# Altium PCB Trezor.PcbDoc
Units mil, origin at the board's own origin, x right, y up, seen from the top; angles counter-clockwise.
Board outline 3500 x 3250 mil, 2 copper layers (Top, Bottom), stack 62 mil thick; 36 components, 17 nets, 131 pads, 2 vias.
Unrouted connection lines stored in the file: 20.
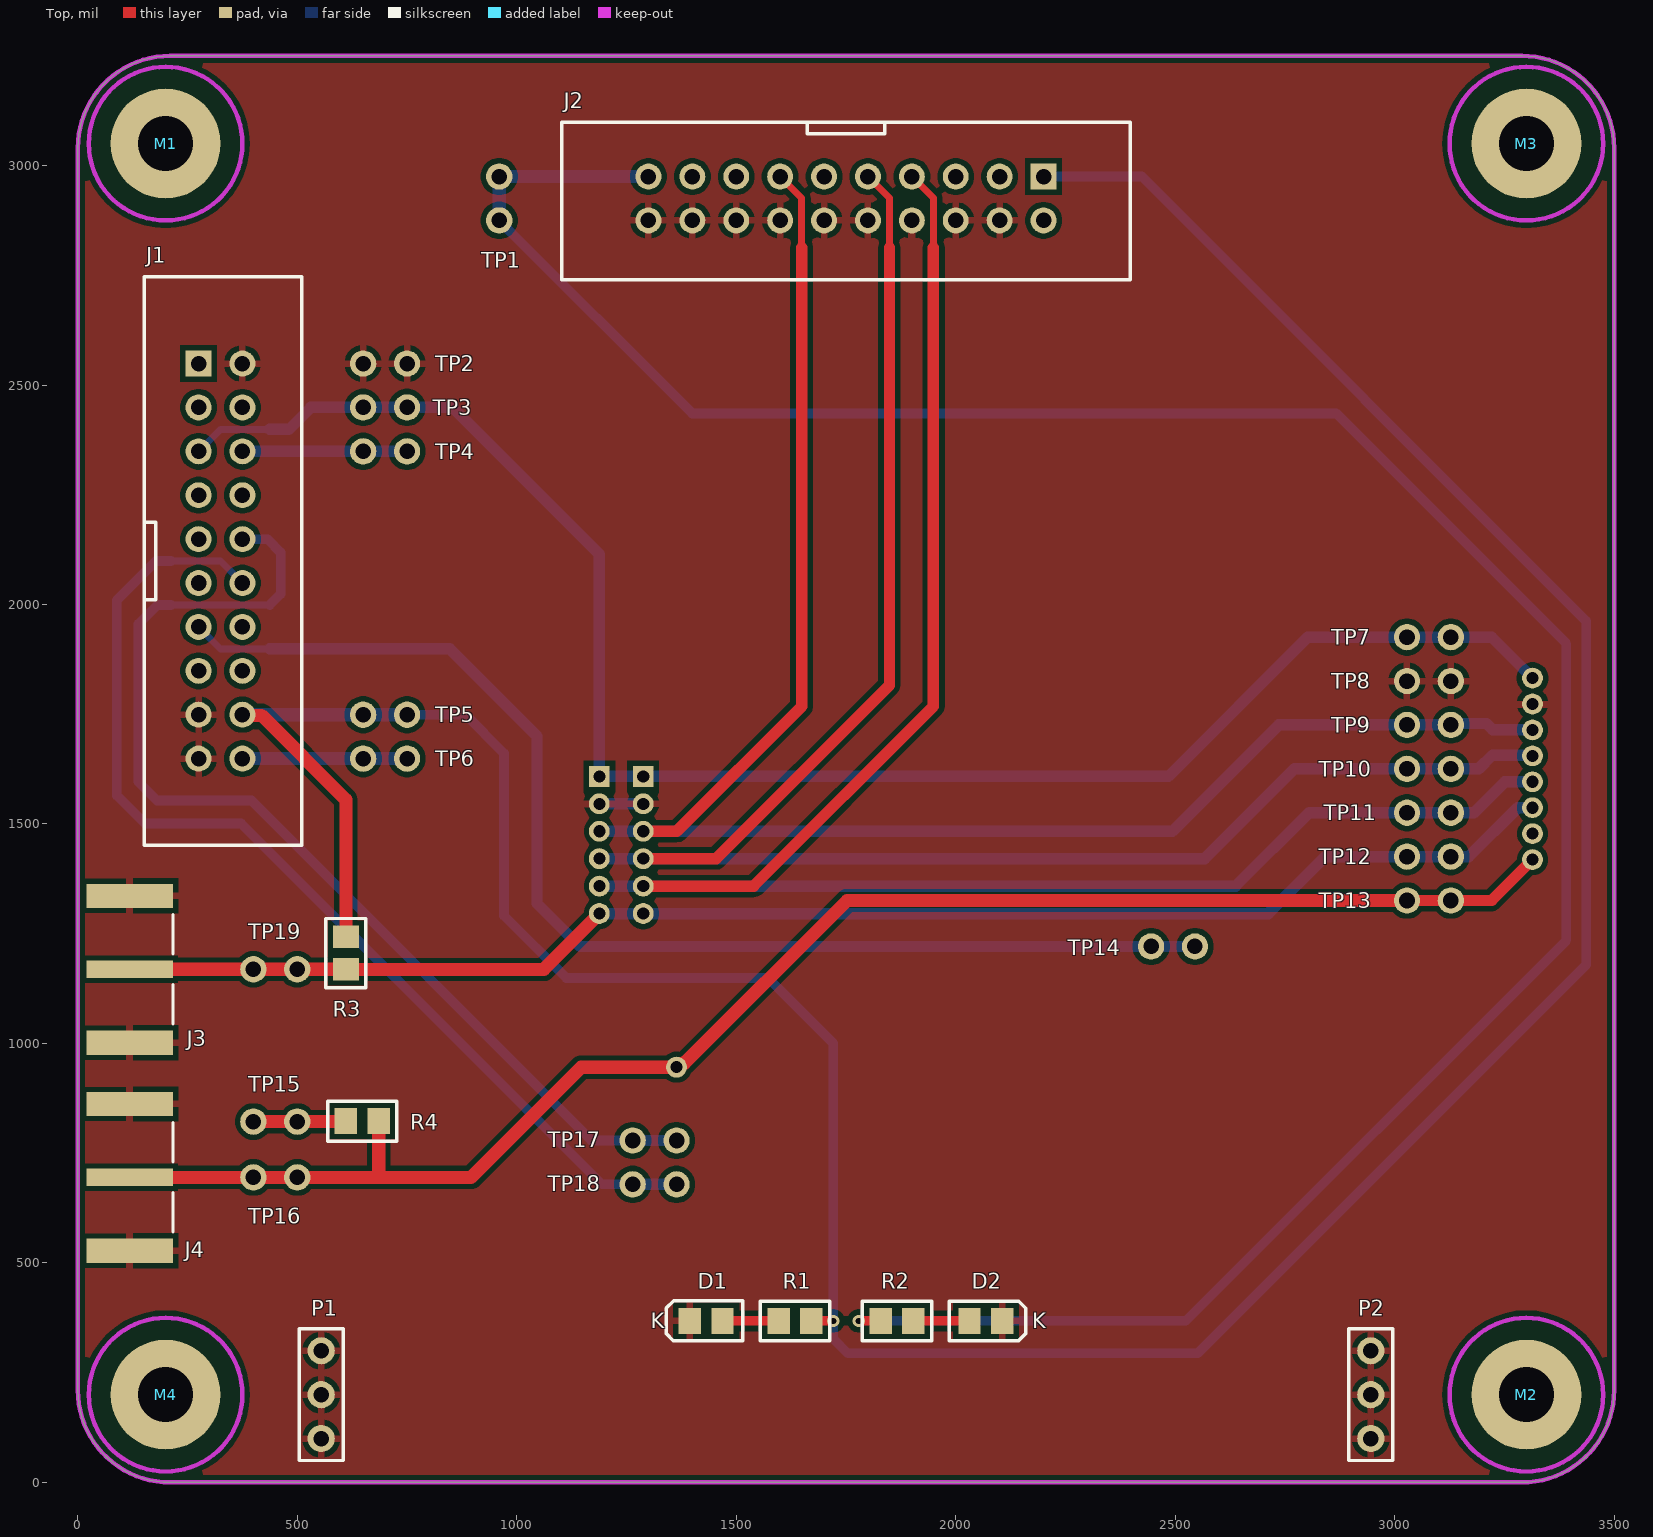
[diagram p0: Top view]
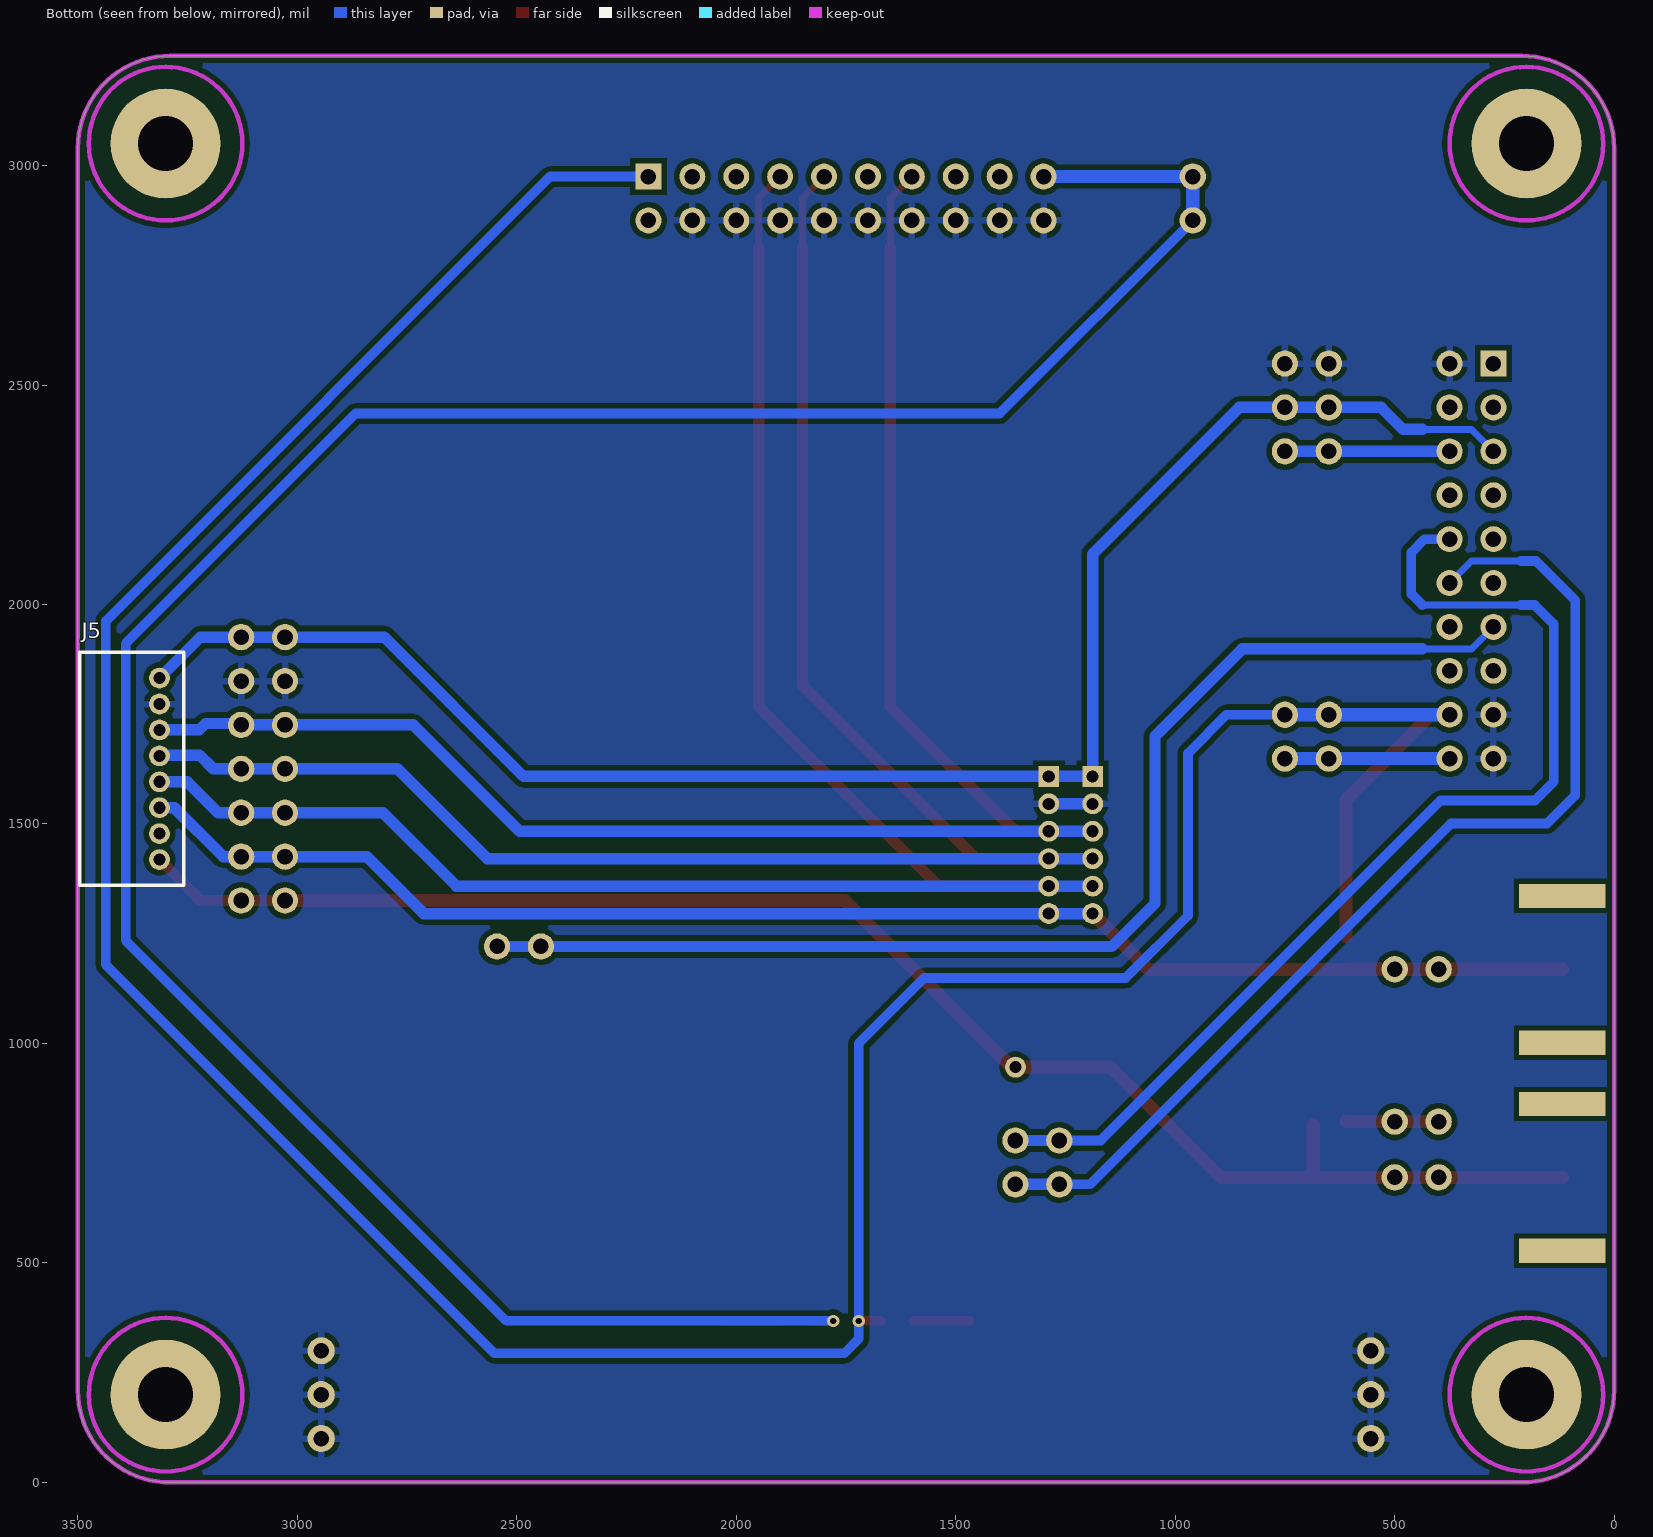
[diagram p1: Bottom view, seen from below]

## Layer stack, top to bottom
Top Solder: solder mask 0.4, Solder Resist, Dk 3.5
Top: signal copper 1.4
Dielectric1: core 59.2, FR-4, Dk 4.8
Bottom: signal copper 1.4
Bottom Solder: solder mask 0.4, Solder Resist, Dk 3.5

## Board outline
0,210 0,3040 cw(c210,3040) 210,3250 3290,3250 cw(c3290,3040) 3500,3040 3500,210 cw(c3290,210) 3290,0 210,0 cw(c210,210)

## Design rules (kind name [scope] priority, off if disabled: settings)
Clearance Clearance_1 [InPolygon] p1: gap=12 ignorepadtopadclearanceinfootprint=FALSE except(0: Arc-Hole Track-Hole SMDPad-Hole THPad-Hole Via-Hole Fill-Hole Poly-Hole Region-Hole Text-Hole)
Clearance [All] p2: gap=10 ignorepadtopadclearanceinfootprint=FALSE
ComponentClearance [All] p1 off: gap=0 collisioncheckmode=3 verticalgap=10 showdistances=FALSE
FabricationTestPointUsage TestPointUsage [All] p1: valid=0 allowmultiple=FALSE
FabricationTestpoint Testpoint [All] p1: side=3 testpointundercomponent=TRUE minsize=40 maxsize=100 preferedsize=60 minholesize=0 maxholesize=40 preferedholesize=32 testpointgrid=1 allowsidetop=TRUE allowsidebottom=TRUE usegrid=TRUE gridtolerance=0.01
HoleSize [All] p1: absolutevalues=TRUE maxlimit=250 minlimit=10 maxpercent=80.000 minpercent=20.000
MinimumAnnularRing [All] p1: minimumring=7
PlaneClearance [All] p1: clearance=12
PlaneConnect [All] p1: planeconnectstyle=Relief reliefexpansion=12 reliefentries=4 reliefconductorwidth=12 reliefairgap=12
PolygonConnect [IsVia] p1: connectstyle=Direct reliefconductorwidth=10 reliefentries=4 polygonreliefangle="90 Angle" airgapwidth=10
PolygonConnect PolygonConnect_1 [All] p2: connectstyle=Relief reliefconductorwidth=16 reliefentries=4 polygonreliefangle="90 Angle" airgapwidth=12
RoutingVias [All] p1: holewidth=14 width=28 viastyle="Through Hole" minholewidth=14 minwidth=28 maxholewidth=14 maxwidth=28
SilkToSolderMaskClearance SilkscreenOverComponentPads [IsPad] p1: minsilkscreentomaskgap=10 clearancetoexposedcopper=TRUE
SolderMaskExpansion SolderMaskExpansion_1 [(IsVia)] p1: expansion=-14 istentingtop=FALSE
SolderMaskExpansion [All] p2: expansion=4 istentingtop=FALSE
SupplyNets "Schematic Supply Nets_3" [InNet('3V3_CW')] p1: voltage=0.000
SupplyNets "Schematic Supply Nets_2" [InNet('GND')] p2: voltage=0.000
SupplyNets "Schematic Supply Nets_1" [InNet('5V0_JLINK')] p3: voltage=0.000
SupplyNets "Schematic Supply Nets" [InNet('5V0_CW')] p4: voltage=0.000
Width [All] p1: maxlimit=32 minlimit=12 preferedwidth=12 minimp=50.000000 maximp=50.000000 favimp=50.000000
23 further rules are at their usual default settings.

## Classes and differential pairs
component class Trezor: D1 D2 J1 J2 J3 J5 P1 P2 R1 R2 R3 TP1 TP2 TP3 TP4 TP5 TP6 TP7 TP8 TP9 TP10 TP11 TP12 TP13 TP14 TP15 TP16 TP17 TP18 TP19

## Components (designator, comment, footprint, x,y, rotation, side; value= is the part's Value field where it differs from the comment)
D1 "LED" "CC2012-0805 LED" 1431.26,368 r180 top
D2 "LED" "CC2012-0805 LED" 2068.76,368 r0 top
J1 "N2520-6002-RB" "HDR2X10 - SHROUD" 275,2549 r270 top locked
J2 "N2520-6002-RB" "HDR2X10 - SHROUD" 2200,2975 r180 top locked
J3 "32K145-400L5" ROS-32K145-400L5_V#1 20,1169 r90 top locked
J4 "32K145-400L5" ROS-32K145-400L5_V#2 20,695 r90 top locked
J5 "JST S8B-ZR" JST-S8B-ZR 3314,1419 r90 bottom locked
M1 "Comment" MOUNTING-HOLE-4-40 200,3050 r0 top
M2 "Comment" MOUNTING-HOLE-4-40 3300,200 r0 top
M3 "Comment" MOUNTING-HOLE-4-40 3300,3050 r0 top
M4 "Comment" MOUNTING-HOLE-4-40 200,200 r0 top
P1 "Header 3" HEADER3 554.5,300 r270 top locked
P2 "Header 3" HEADER3 2945.5,300 r270 top locked
R1 "Res1" CC2012-0805 1633.76,368 r180 top value=10k
R2 "Res1" CC2012-0805 1866.26,368 r0 top value=10k
R3 "Res1" CC2012-0805 610.6,1206 r270 top value="10 ohm"
R4 "Res1" CC2012-0805 648,823 r0 top value=DNP
TP1 "TESTPOINT" "TESTPOINT - DOUBLE"#1 960,2975 r270 top
TP2 "TESTPOINT" "TESTPOINT - DOUBLE"#1 650,2549 r0 top
TP3 "TESTPOINT" "TESTPOINT - DOUBLE"#1 650,2449 r0 top
TP4 "TESTPOINT" "TESTPOINT - DOUBLE"#1 650,2349 r0 top
TP5 "TESTPOINT" "TESTPOINT - DOUBLE"#1 650,1749 r0 top
TP6 "TESTPOINT" "TESTPOINT - DOUBLE"#1 750,1649 r180 top
TP7 "TESTPOINT" "TESTPOINT - DOUBLE"#1 3028,1925.69 r0 top
TP8 "TESTPOINT" "TESTPOINT - DOUBLE"#1 3028,1825.69 r0 top
TP9 "TESTPOINT" "TESTPOINT - DOUBLE"#1 3028,1725.69 r0 top
TP10 "TESTPOINT" "TESTPOINT - DOUBLE"#1 3028,1625.69 r0 top
TP11 "TESTPOINT" "TESTPOINT - DOUBLE"#1 3028,1525.69 r0 top
TP12 "TESTPOINT" "TESTPOINT - DOUBLE"#1 3028,1425.69 r0 top
TP13 "TESTPOINT" "TESTPOINT - DOUBLE"#1 3028,1325.69 r0 top
TP14 "TESTPOINT" "TESTPOINT - DOUBLE"#1 2445,1221 r0 top
TP15 "TESTPOINT" "TESTPOINT - DOUBLE"#1 400,822 r0 top
TP16 "TESTPOINT" "TESTPOINT - DOUBLE"#1 400,695 r0 top
TP17 "TESTPOINT" "TESTPOINT - DOUBLE"#1 1264,779 r0 top
TP18 "TESTPOINT" "TESTPOINT - DOUBLE"#1 1264,679 r0 top
TP19 "TESTPOINT" "TESTPOINT - DOUBLE"#2 400,1167 r0 top

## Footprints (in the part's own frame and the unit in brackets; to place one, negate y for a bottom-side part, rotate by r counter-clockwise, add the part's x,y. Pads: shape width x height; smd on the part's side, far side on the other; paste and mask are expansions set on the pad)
CC2012-0805 [mm]
  rect 1.3x1.5 smd: 1(-0.95,0) 2(0.95,0)
  silkscreen extent -2,-1.15 2,1.15
"CC2012-0805 LED" [mm]
  rect 1.3x1.5 smd: 1(-0.95,0) 2(0.95,0)
  silkscreen extent -2.12,-1.16 2.3,1.14
"HDR2X10 - SHROUD" [mm] "3M N2520-6002-RB CONN HEADER VERT 20POS 2.54MM"
  rect 1.5x1.5 hole 0.9: 1(0,0)
  round 1.5 hole 0.9: 2(0,2.54) 3(2.54,0) 4(2.54,2.54) 5(5.08,0) 6(5.08,2.54) 7(7.62,0) 8(7.62,2.54) 9(10.16,0) 10(10.16,2.54) 11(12.7,0) 12(12.7,2.54) 13(15.24,0) 14(15.24,2.54) 15(17.78,0) 16(17.78,2.54) 17(20.32,0) 18(20.32,2.54) 19(22.86,0) 20(22.86,2.54)
  silkscreen extent -5.02,-3.13 27.88,5.97
HEADER3 [mil]
  round 62 hole 35.43: 1(0,0) 2(100,0) 3(200,0)
  silkscreen extent -50,-50 250,50
JST-S8B-ZR [mm]
  round 1.2 hole 0.7: 1(10.5,0) 2(9,0) 3(7.5,0) 4(6,0) 5(4.5,0) 6(3,0) 7(1.5,0) 8(0,0)
  silkscreen extent -1.5,-1.4 12,4.6
MOUNTING-HOLE-4-40 [mil] "Mounting Hole w/ Annular Ring US #4-40/Metric M3"
  round 250 hole 125: 0(0,0)
  Keep-Out Layer circle w10: c0,0 r175
ROS-32K145-400L5_V#1 [mm] "SMA Right Angle Jack, Edge Mount, 14.25x9.5x4.46mm, Rosenberger Recommended"
  rect 1x5 smd paste-2539.97: 1(0,-2.5)
  rect 1.4x5 smd paste-2539.97: MP(-4.25,-2.5) MP(4.25,-2.5)
  rect 1.4x5 smd far side paste-2: ""(-4.25,-2.5) ""(4.25,-2.5)
  silkscreen extent -3.15,-5 3.15,-5, body extent -4.75,-4.75 4.75,9.5, height 4.46
ROS-32K145-400L5_V#2 [mm] "SMA Right Angle Jack, Edge Mount, 14.25x9.5x4.46mm, Rosenberger Recommended"
  rect 1x5 smd: 1(0,-2.5)
  rect 1.4x5 smd: MP(-4.25,-2.5) MP(4.25,-2.5)
  rect 1.4x5 smd far side: ""(-4.25,-2.5) ""(4.25,-2.5)
  silkscreen extent -3.15,-5 3.15,-5, body extent -4.75,-4.75 4.75,9.5, height 4.46
"TESTPOINT - DOUBLE"#1 [mil]
  round 60 hole 35.43: 1(0,0) 1(100,0)
"TESTPOINT - DOUBLE"#2 [mil]
  round 60 hole 35.43: 1(0,2) 1(100,2)

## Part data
D1 D2: library part LED0, "Typical LED"
J1 J2: library part "Header 10X2", "Header, 10-Pin, Dual row"
J3 J4: "SMA Right Angle Jack, Edge Mount, Up to 18 GHz, -55 to 155 degC"
J5: library part "Header 8", "Header, 8-Pin"
P1 P2: "Header, 3-Pin"
R1 R2 R3 R4: "Resistor"

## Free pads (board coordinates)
  rect 47.56x47.56 / inner round 43.94 / far side rect 47.56x47.56 hole 27.56: 1(1188,1608.5) 1(1288,1608.5)
  round 47.56 hole 27.56: 2(1188,1546) 2(1288,1546) 3(1188,1483.5) 3(1288,1483.5) 4(1188,1421) 4(1288,1421) 5(1188,1358.5) 5(1288,1358.5) 6(1188,1296) 6(1288,1296) 6(1364,946)

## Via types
v1: diameter 28, hole 14, Top to Bottom, 2 vias

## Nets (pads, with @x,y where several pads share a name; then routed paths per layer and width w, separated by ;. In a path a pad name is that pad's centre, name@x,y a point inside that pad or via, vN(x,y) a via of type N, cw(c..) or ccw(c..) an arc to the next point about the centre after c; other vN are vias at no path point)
3V3_CW: J1.18 J2.1 R1.1 R3.1 TP5.1 | length 7756.4
  Top w22: R1.1 v1(1721.01,368)
  Top w30: J1.18 376.7,1747.3 418.7,1747.3 610.6,1555.4 R3.1
  Bottom w22: TP5.1@750,1749 883,1749 971,1661 971,1291 1113,1149 1572,1149 1721.01,999.99 v1@1721.01,369.62 ; v1(1721.01,368) 1721.01,326.99 1754,294 2551,294 3436,1179 3436,1963 2424,2975 J2.1
  Bottom w30: J1.18 650,1749 TP5.1@750,1749
5V0_CW: J1.20 TP6.1 | length 375
  Bottom w30: J1.20 650,1649 TP6.1@750,1649
5V0_JLINK: J2.19 R2.1 TP1.1 | length 5967.3
  Top w22: v1(1779,368) R2.1
  Bottom w22: TP1.1@960,2875 1400,2435 2867,2435 3391,1911 3391,1235 2524,368 v1(1779,368)
  Bottom w30: TP1.1@960,2875 960,2975 J2.19
GND: D1.2 D2.2 J1.2 J1.17 J1.19 J2.4 J2.6 J2.8 J2.10 J2.12 J2.14 J2.16 J2.18 J2.20 J3.MP J4.MP J5.2 P1.1 P1.2 P1.3 P2.1 P2.2 P2.3 pad.2 TP2.1 TP8.1 | length 100
  Bottom w26: pad.2@1188,1546 pad.2@1288,1546
HS2: J1.6 TP4.1 | length 375
  Bottom w26: J1.6 650,2349 TP4.1@750,2349
NetD1_1: D1.1 R1.2 | length 127.7
  Top w22: D1.1 R1.2
NetD2_1: D2.1 R2.2 | length 127.7
  Top w22: R2.2 D2.1
NetR4_1: R4.1 TP15.1 | length 211
  Top w30: TP15.1@400,822 500,822 609.6,822 R4.1
NRST: J1.5 J5.1 pad.1 TP3.1 TP7.1 | length 3895.3
  Bottom w16: J1.5 325,2399 437,2399
  Bottom w26: 437,2399 481,2399 531,2449 650,2449 750,2449 854,2449 1188,2115 1188,1608.5 1288,1608.5 2484.5,1608.5 2801.69,1925.69 3028,1925.69 3128,1925.69 3220.69,1925.69 J5.1
PDIC: J1.13 TP14.1 | length 2797.9
  Top w22: J1.13@272.79,1946.79 J1.13
  Bottom w16: J1.13 325,1899 437,1899
  Bottom w26: 437,1899 847,1899 1046,1700 1046,1319 1144,1221 2445,1221 TP14.1@2545,1221
SCA_3V3: J3.1 J5.6 pad.6@1188,1296 pad.6@1288,1296 R3.2 TP12.1 TP19.1 | length 3347.8
  Top w26: 1061.6,1168.6 1061.6,1169.6
  Top w30: J3.1 400,1169 500,1169 R3.2@609.6,1169 ; R3.2 1061.6,1168.6 ; 1061.6,1169.6 pad.6@1188,1296
  Bottom w26: pad.6@1188,1296 1288,1296 2712,1296 2841.69,1425.69 3028,1425.69 3128,1425.69 3168.69,1425.69 3280.11,1537.11 J5.6
SCA_VCORE: J4.1 J5.8 pad.6@1364,946 R4.2 TP13.1 TP16.1 | length 3615.6
  Top w26: TP13.1@3028,1325.69 3128,1325.69 3220.69,1325.69 J5.8
  Top w30: J4.1 400,695 500,695 685,695 ; R4.2@685.4,815 685.4,695.4 685,695 ; TP13.1@3028,1325.69 1752.69,1325.69 1381.78,954.78 1377.53,954.78 1368.75,946 1147,946 896,695 685,695
SWCLK: J2.9 J5.4 pad.4 TP10.1 | length 4128.4
  Top w16: J2.9 1849,2926 1849,2813
  Top w26: pad.4@1288,1421 1454,1421 1849,1816 1849,2813 ; J5.4@3312.22,1657 J5.4
  Bottom w26: pad.4@1188,1421 1288,1421 2567,1421 2771.69,1625.69 3028,1625.69 3128,1625.69 3191.69,1625.69 3223,1657 J5.4@3312.22,1657
SWDIO: J2.7 J5.5 pad.5 TP11.1 | length 4282.4
  Top w16: J2.7 1949,2926 1949,2813
  Top w26: pad.5@1288,1358.5 1539.5,1358.5 1949,1768 1949,2813
  Bottom w26: pad.5@1188,1358.5 1288,1358.5 2637.5,1358.5 2804.69,1525.69 3028,1525.69 3128,1525.69 3180.69,1525.69 3251.17,1596.17 J5.5
SWO: J2.13 J5.3 pad.3 TP9.1 | length 3939.9
  Top w16: J2.13 1649,2926 1649,2813
  Top w26: pad.3@1288,1483.5 1364.5,1483.5 1649,1768 1649,2813 ; TP9.1@3128,1725.69 TP9.1@3131.31,1729
  Bottom w26: pad.3@1188,1483.5 1288,1483.5 2493.5,1483.5 2735.69,1725.69 3028,1725.69 TP9.1@3128,1725.69 ; TP9.1@3131.31,1729 3209,1729 3223.72,1714.28 J5.3
TIO1: J1.10 TP17.1 | length 2471
  Bottom w16: 213,1999 437,1999
  Bottom w22: 213,1999 181,1999 138,1956 138,1596 180.5,1553.5 395.5,1553.5 1170,779 TP17.1@1264,779 ; J1.10 432,2149 462,2119 462,2024 437,1999
  Bottom w26: TP17.1@1264,779 TP17.1@1364,779
TIO2: J1.12 TP18.1 | length 2430.6
  Bottom w16: 213,2099 325,2099 J1.12
  Bottom w22: 213,2099 178,2099 89,2010 89,1565 153,1501 372,1501 1194,679 TP18.1@1264,679
  Bottom w26: TP18.1@1264,679 TP18.1@1364,679
pads on no net: J1.1 J1.3 J1.4 J1.7 J1.8 J1.9 J1.11 J1.14 J1.15 J1.16 J2.2 J2.3 J2.5 J2.11 J2.15 J2.17 J3. J4. J5.7 M1.0 M2.0 M3.0 M4.0

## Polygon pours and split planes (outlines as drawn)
GND on Bottom "GND_L02_P001" (solid, remove dead copper, pour order 3): 0,3250 3500,3250 3500,0 0,0
GND on Top "GND_L01_P001" (solid, remove dead copper, pour order 4): 0,3250 3500,3250 3500,0 0,0

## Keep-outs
Keep-Out Layer:
  the board outline again, w10

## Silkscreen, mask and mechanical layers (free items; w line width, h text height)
Top Overlay:
  text "K" at 1304.76,351 h35
  text "K" at 2173.76,351 h35
Silkscreen Top:
  lines w8: 1225,1191.5 1225,2509.5 1229,2531.5 1242,2551.5 1261,2563.5 1284,2568.5 1463,2568.5 1485,2561.5 1499,2544.5 1508,2530.5 1521,2518.5 1536,2511.5 1553,2509.5 1947,2509.5 1964,2511.5 1979,2518.5 1992,2530.5 2001,2544.5 2015,2561.5 2037,2568.5 2216,2568.5 2239,2563.5 2258,2551.5 2271,2532.5 2275,2509.5 2275,1191.5 2273,1175.5 2267,1160.5 2186,1026.5 2165,1034.5 2142,1033.5 2121,1023.5 2105,1006.5 2009,845.5 2001,823.5 2002,800.5 2012,779.5 2029,764.5 1948,629.5 1927,608.5 1898,601.5 1603,601.5 1573,608.5 1552,629.5 1465,774.5 1482,789.5 1492,810.5 1493,833.5 1485,855.5 1401,996.5 1386,1013.5 1365,1022.5 1342,1024.5 1320,1016.5 1233,1160.5 1227,1175.5 1225,1191.5
  text "J-LINK" at 2476,2824 h35 r90
  text "CW" at 294,2790 h35
  text "J-LINK" at 864,2765 h35
  text "+5V" at 908,2693 h35
  text "GND" at 831,2531 h35
  text "NRST" at 831,2431 h35
  text "HS2" at 831,2331 h35
  text "NRST" at 2812.93,1907.69 h35
  text "GND" at 2847.92,1807.69 h35
  text "CW" at 831,1731 h35
  text "+3." at 925.87,1730.77 h35
  text "3V" at 1014,1730.77 h35
  text "TDO/SWO" at 2707.97,1707.69 h35
  text "CW +5V" at 831,1631 h35
  text "TCK/SWDCLK" at 2603,1607.69 h35
  text "TMS/SWDIO" at 2643.82,1507.69 h35
  text "VDD" at 2847.92,1407.69 h35
  text "Glitch Out" at 2632.16,1307.69 h35
  text "SCA +3.3V" at 694,1227 h35
  text "BOOT0" at 2631.74,1202.34 h35
  text "SCA VCORE" at 395,899 h35
  text "PA9" at 1084.08,761 h35
  text "Glitch In" at 578,678 h35
  text "PA10" at 1054.92,661 h35
  text "CW" at 1408.13,435.23 h35
  text "+3." at 1503,435 h35
  text "3V" at 1591,435 h35
  text "J-LINK +5V" at 1801,435 h35
  text "GND" at 508,385 h35
  text "GND" at 2898,385 h35
  text "Trezor One In-Situ Adapter" at 1162,126 h90
Silkscreen Bottom:
  text "Joe Grand (@joegrand)" at 2103,166 h35
  text "Lennert Wouters (@lennertwo)" at 2213.8,84 h35
Board Shape:
  the board outline again, w10
Drill Drawing:
  drawing of 1722 lines, arcs and shapes, not listed
  text "FABRICATION / ASSEMBLY NOTES:" at -565.83,6384 h59.06
  text "(UNLESS OTHERWISE SPECIFIED)" at -565.83,6284 h59.06
  text "1. MATERIAL: EPOXY GLASS LAMINATE FR-4" at -565.83,6084 h59.06
  text "FINISHED COPPER WEIGHT SHALL BE 1 OZ ON ALL LAYERS" at -465.83,5984 h59.06
  text "2. NUMBER OF ELECTRICAL LAYERS: 2" at -565.83,5784 h59.06
  text "3. THICKNESS: 0.062\" (FINISHED)" at -561.83,5584 h59.06
  text "4. FINISH: IMMERSION PLATE EXPOSED AREAS AFTER APPLYING SOLDER MASK WITH ELECTROLESS NICKEL IMMERSION GOLD" at -560,5376 h59.06
  text "5. SOLDER MASK: LIQUID PHOTOIMAGEABLE SOLDER MASK PER IPC-SM-840" at -560,5176 h59.06
  text "COLOR ANY, 10/ 50um THK, BOTH SIDES, AFTER PLATING. REGISTRATION TO BE WITHIN +/- 50um" at -445,5076 h59.06
  text "OF THE ASSOCIATED CIRCUIT LAYER." at -445,4976 h59.06
  text "6. SILKSCREEN: SILKSCREEN BOTH SIDES USING WHITE NONCONDUCTIVE INK." at -560,4776 h59.06
  text "7. BARE BOARD ELECTRICAL TEST: 100% SCHEMATIC NETLIST TEST COVERAGE REQUIRED." at -560,4576 h59.06
  text "8. RoHS: PARTS SHALL BE RoHS COMPLIANT PER EUROPEAN UNION DIRECTIVE 2002/95/EC." at -560,4376 h59.06
  text "9. THE BOARD MUST BE LEAD-FREE ASSEMBLY PROCESS COMPATIBLE AND BE ABLE TO HANDLE A MINIMUM" at -560,4176 h59.06
  text "OF 5 CYCLES AT 260 DEGREES CELSIUS" at -437,4076 h59.06
  text "10. NO QA/QC/TEST/FAB MARKINGS ANYWHERE ON THE PCB" at -560,3876 h59.06
  text ".PCB_FILE_NAME_NO_PATH" at -905.7,-955.88 h70
  text "COMPANY:" at 922.71,-1181.75 h39.37
  text "Grand Idea Studio, Inc." at 1058.75,-1310 h49.21
  text "TITLE:" at 922.71,-1496.71 h39.37
  text "Trezor One In-Situ Adapter Board" at 1058.75,-1621 h49.21
  text "DRAWN:" at 922.71,-1811.67 h39.37
  text "Joe Grand" at 1058.75,-1933 h49.21
  text "DESIGN FILES DISTRIBUTED UNDER A" at -792.08,-1939.39 h34.45
  text "CREATIVE COMMONS ATTRIBUTION 4.0 INTERNATIONAL LICENSE" at -792.08,-2018.13 h34.45
  text "2024 cc by 4.0" at -796.33,-2101.28 h34.45
  text "ISSUE:" at 922.71,-2126.63 h39.37
  text "DATE:" at 1395.16,-2126.63 h39.37
  text ".PRINT_DATE" at 1691.3,-2148.88 h49.21
  text "B" at 1192.3,-2154.88 h49.21
  text ".LEGEND" at 3028,-2186 h60

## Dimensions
3290,3250 to 3290,0 on Drill Drawing
0,3040 to 3500,3040 on Drill Drawing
